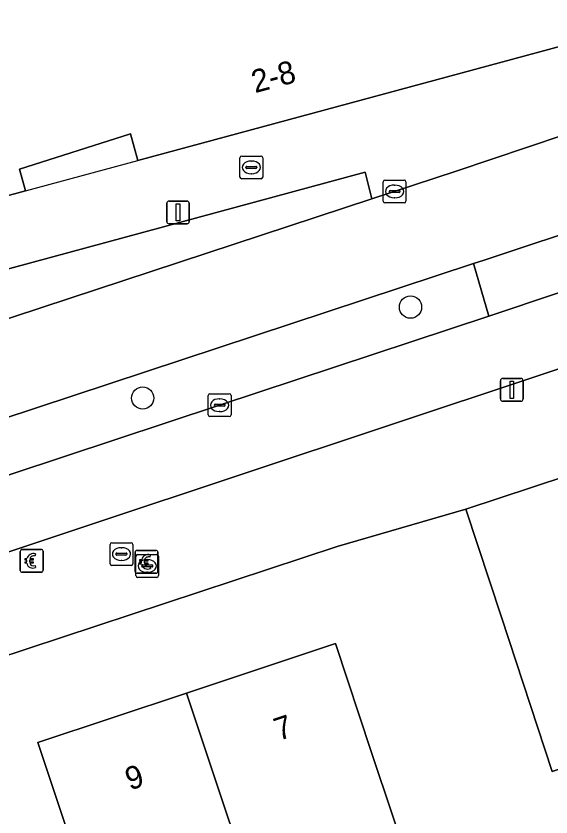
# Model space of a CAD drawing. Extents: x 161087 to 161926, y 382572 to 383873.
# Drawn here: x 161653.49 to 161676.98, y 382778.05 to 382813.22 of the extents above; entities that cross this region are included whole.
import ezdxf

# ---------------------------------------------------------------- set-up
doc = ezdxf.new("R2010")
doc.units = 0
for name, color, linetype in [('IMGEO_Berm_groen', 7, 'Continuous'), ('IMGEO_Berm_halfverhard', 7, 'Continuous'), ('IMGEO_Betaalautomaat', 7, 'Continuous'), ('IMGEO_Boom', 7, 'Continuous'), ('IMGEO_Brandkraan', 7, 'Continuous'), ('IMGEO_Erf', 7, 'Continuous'), ('IMGEO_Fietspad_gesloten', 7, 'Continuous'), ('IMGEO_Kolk', 7, 'Continuous'), ('IMGEO_Lichtmast', 7, 'Continuous'), ('IMGEO_Pand', 7, 'Continuous'), ('IMGEO_Pand_nummerreeks', 7, 'Continuous'), ('IMGEO_Pand_overbouw', 7, 'Continuous'), ('IMGEO_Rijbaan_lokaal_gesloten', 7, 'Continuous'), ('IMGEO_Rioolput', 7, 'Continuous'), ('IMGEO_Voetpad_open', 7, 'Continuous')]:
    doc.layers.add(name, color=color, linetype=linetype)

msp = doc.modelspace()

# ---------------------------------------------------------------- linework, layer by layer
at = {"layer": 'IMGEO_Berm_groen'}
for points in [[(161669.12, 382805.198), (161668.823, 382806.36), (161642.785, 382799.309), (161642.68, 382799.282), (161643.487, 382796.752), (161643.598, 382796.789), (161646.117, 382797.624)], [(161674.253, 382800.049), (161673.571, 382802.349), (161647.995, 382793.914), (161648.757, 382791.611), (161662.429, 382796.134)]]:
    msp.add_lwpolyline(points, close=True, dxfattribs=at)
at = {"layer": 'IMGEO_Berm_halfverhard'}
msp.add_lwpolyline([(161679.239, 382804.225), (161674.047, 382802.506), (161673.571, 382802.349), (161674.253, 382800.049), (161674.729, 382800.207), (161679.006, 382801.638), (161679.974, 382801.957)], close=True, dxfattribs=at)
at = {"layer": 'IMGEO_Betaalautomaat'}
for p, q in [((161653.675, 382788.875), (161653.675, 382789.716)), ((161653.675, 382789.716), (161653.675, 382788.875)), ((161653.75, 382789.799), (161654.591, 382789.799)), ((161654.591, 382789.799), (161653.75, 382789.799)), ((161654.674, 382789.725), (161654.674, 382788.884)), ((161654.674, 382788.884), (161654.674, 382789.725)), ((161658.717, 382788.832), (161658.717, 382789.673)), ((161658.717, 382789.673), (161658.717, 382788.832)), ((161658.792, 382789.756), (161659.633, 382789.756)), ((161659.633, 382789.756), (161658.792, 382789.756)), ((161659.716, 382789.682), (161659.716, 382788.841)), ((161659.716, 382788.841), (161659.716, 382789.682)), ((161653.958, 382789.263), (161653.958, 382789.331)), ((161654.079, 382789.331), (161654.079, 382789.263)), ((161654.337, 382789.604), (161654.32, 382789.504)), ((161659.379, 382789.561), (161659.362, 382789.461)), ((161654.324, 382789.098), (161654.346, 382789.011)), ((161659, 382789.22), (161659, 382789.288)), ((161659.121, 382789.288), (161659.121, 382789.22)), ((161659.366, 382789.055), (161659.388, 382788.968)), ((161654.6, 382788.8), (161653.759, 382788.8)), ((161653.759, 382788.8), (161654.6, 382788.8)), ((161659.642, 382788.757), (161658.801, 382788.757)), ((161658.801, 382788.757), (161659.642, 382788.757))]:
    msp.add_line(p, q, dxfattribs=at)
for points in [[(161653.958, 382789.331), (161653.889, 382789.331), (161653.889, 382789.4), (161653.968, 382789.4)], [(161654.09, 382789.4), (161654.237, 382789.4), (161654.237, 382789.331), (161654.079, 382789.331)], [(161659, 382789.288), (161658.931, 382789.288), (161658.931, 382789.357), (161659.01, 382789.357)], [(161659.132, 382789.357), (161659.279, 382789.357), (161659.279, 382789.288), (161659.121, 382789.288)], [(161653.963, 382789.194), (161653.889, 382789.194), (161653.889, 382789.263), (161653.958, 382789.263)], [(161654.079, 382789.263), (161654.237, 382789.263), (161654.237, 382789.194), (161654.093, 382789.194)], [(161659.005, 382789.151), (161658.931, 382789.151), (161658.931, 382789.22), (161659, 382789.22)], [(161659.121, 382789.22), (161659.279, 382789.22), (161659.279, 382789.151), (161659.135, 382789.151)]]:
    msp.add_lwpolyline(points, dxfattribs=at)
for centre, radius, start, end in [((161653.753, 382789.722), 0.0779, 92.4484, 184.2845), ((161653.753, 382789.722), 0.0779, 92.4484, 184.2845), ((161654.597, 382789.722), 0.0779, 2.4484, 94.2845), ((161654.597, 382789.722), 0.0779, 2.4484, 94.2845), ((161658.795, 382789.679), 0.0779, 92.4484, 184.2845), ((161658.795, 382789.679), 0.0779, 92.4484, 184.2845), ((161659.639, 382789.679), 0.0779, 2.4484, 94.2845), ((161659.639, 382789.679), 0.0779, 2.4484, 94.2845), ((161654.251, 382789.324), 0.293, 73.014, 165.0139), ((161654.257, 382789.337), 0.179, 69.3236, 159.5683), ((161659.293, 382789.281), 0.293, 73.014, 165.0139), ((161659.299, 382789.294), 0.179, 69.3236, 159.5683), ((161654.224, 382789.249), 0.267, 191.8096, 297.0389), ((161654.257, 382789.264), 0.179, 202.7625, 291.8693), ((161659.266, 382789.206), 0.267, 191.8096, 297.0389), ((161659.299, 382789.221), 0.179, 202.7625, 291.8693), ((161653.753, 382788.878), 0.0779, 182.4484, 274.2845), ((161653.753, 382788.878), 0.0779, 182.4484, 274.2845), ((161654.597, 382788.878), 0.0779, 272.4484, 4.2845), ((161654.597, 382788.878), 0.0779, 272.4484, 4.2845), ((161658.795, 382788.835), 0.0779, 182.4484, 274.2845), ((161658.795, 382788.835), 0.0779, 182.4484, 274.2845), ((161659.639, 382788.835), 0.0779, 272.4484, 4.2845), ((161659.639, 382788.835), 0.0779, 272.4484, 4.2845)]:
    msp.add_arc(centre, radius, start, end, dxfattribs=at)
at = {"layer": 'IMGEO_Boom'}
for centre in [(161670.812, 382800.441), (161659.053, 382796.447)]:
    msp.add_circle(centre, 0.489, dxfattribs=at)
at = {"layer": 'IMGEO_Brandkraan'}
for p, q in [((161658.749, 382788.65), (161658.749, 382789.502)), ((161658.824, 382789.576), (161659.676, 382789.576)), ((161659.237, 382789.356), (161659.262, 382789.356)), ((161659.75, 382789.502), (161659.75, 382788.65)), ((161659.008, 382789.07), (161659.008, 382789.082)), ((161659.446, 382789.033), (161659.048, 382789.033)), ((161659.051, 382789.119), (161659.449, 382789.119)), ((161659.492, 382789.082), (161659.492, 382789.07)), ((161659.26, 382788.796), (161659.235, 382788.796)), ((161659.676, 382788.576), (161658.824, 382788.576))]:
    msp.add_line(p, q, dxfattribs=at)
for points in [[(161658.749, 382788.65), (161658.749, 382789.502)], [(161658.824, 382789.576), (161659.676, 382789.576)], [(161659.75, 382789.502), (161659.75, 382788.65)], [(161659.676, 382788.576), (161658.824, 382788.576)]]:
    msp.add_lwpolyline(points, dxfattribs=at)
for centre, radius, start, end in [((161658.826, 382789.5), 0.0765, 91.552, 178.448), ((161658.826, 382789.5), 0.0765, 91.552, 178.448), ((161659.674, 382789.5), 0.0765, 1.552, 88.448), ((161659.674, 382789.5), 0.0765, 1.552, 88.448), ((161659.048, 382789.079), 0.0403, 85.8775, 175.7526), ((161659.045, 382789.069), 0.0366, 178.938, 274.7102), ((161659.449, 382789.076), 0.043, 264.8664, 352.4533), ((161659.453, 382789.081), 0.0386, 1.7309, 96.639), ((161658.826, 382788.652), 0.0765, 181.552, 268.448), ((161658.826, 382788.652), 0.0765, 181.552, 268.448), ((161659.674, 382788.652), 0.0765, 271.552, 358.448), ((161659.674, 382788.652), 0.0765, 271.552, 358.448)]:
    msp.add_arc(centre, radius, start, end, dxfattribs=at)
for centre, major_axis, ratio, start_param, end_param in [((161659.236, 382789.076), (-0.387, 0.002), 0.722429, 4.712389, 7.853982), ((161659.261, 382789.076), (-0.39, 0.002), 0.717154, 1.570796, 4.712389)]:
    msp.add_ellipse(centre, major_axis=major_axis, ratio=ratio, start_param=start_param, end_param=end_param, dxfattribs=at)
at = {"layer": 'IMGEO_Erf'}
msp.add_lwpolyline([(161712.955, 382781.187), (161710.53, 382787.424), (161708.527, 382792.577), (161702.9, 382790.39), (161703.029, 382790.057), (161700.892, 382787.466), (161700.822, 382787.646), (161694.622, 382780.114), (161693.332, 382781.441), (161693.557, 382783.201), (161689.279, 382781.794), (161686.574, 382780.904), (161683.613, 382779.93), (161683.448, 382779.876), (161682.763, 382781.94), (161681.287, 382781.455), (161677.03, 382780.056), (161674.804, 382786.826), (161673.242, 382791.575), (161667.594, 382789.929), (161637.427, 382779.982)], dxfattribs=at)
msp.add_lwpolyline([(161664.779, 382772.083), (161665.682, 382769.375), (161666.021, 382768.356), (161666.195, 382767.836), (161659.658, 382765.658), (161659.642, 382765.708), (161659.485, 382766.178), (161657.275, 382772.813), (161656.021, 382776.578), (161654.442, 382781.321), (161660.975, 382783.496), (161667.512, 382785.673), (161669.091, 382780.929), (161670.995, 382775.209), (161671.424, 382773.92), (161674.213, 382774.896), (161676.279, 382768.99), (161672.96, 382767.829), (161672.097, 382770.294), (161669.494, 382769.426), (161668.449, 382772.563), (161667.962, 382772.401), (161667.74, 382773.069)], close=True, dxfattribs=at)
at = {"layer": 'IMGEO_Fietspad_gesloten'}
for points in [[(161590.845, 382774.955), (161600.424, 382778.175), (161606.867, 382780.274), (161620.39, 382784.782), (161636.138, 382789.999), (161645.193, 382792.972), (161647.376, 382793.71), (161647.995, 382793.914), (161673.571, 382802.349), (161674.047, 382802.506), (161679.239, 382804.225), (161681.775, 382805.065), (161703.785, 382812.521), (161709.459, 382814.438)], [(161687.036, 382811.115), (161680.653, 382809.049), (161672.813, 382806.414), (161669.12, 382805.198), (161646.117, 382797.624), (161643.598, 382796.789), (161643.487, 382796.752), (161637.587, 382794.797), (161636.587, 382794.458), (161636.5, 382794.429), (161633.539, 382793.428), (161627.936, 382791.59), (161605.586, 382784.256), (161599.127, 382782.114), (161588.363, 382778.462)]]:
    msp.add_lwpolyline(points, dxfattribs=at)
at = {"layer": 'IMGEO_Kolk'}
for p, q in [((161663.323, 382806.148), (161663.323, 382807)), ((161663.398, 382807.074), (161664.25, 382807.074)), ((161664.324, 382807), (161664.324, 382806.148)), ((161663.582, 382806.568), (161663.582, 382806.58)), ((161664.02, 382806.531), (161663.622, 382806.531)), ((161663.625, 382806.617), (161664.023, 382806.617)), ((161663.811, 382806.854), (161663.836, 382806.854)), ((161664.066, 382806.58), (161664.066, 382806.568)), ((161663.834, 382806.294), (161663.809, 382806.294)), ((161664.25, 382806.074), (161663.398, 382806.074)), ((161661.928, 382795.708), (161661.928, 382796.56)), ((161662.003, 382796.634), (161662.855, 382796.634)), ((161662.416, 382796.414), (161662.441, 382796.414)), ((161662.929, 382796.56), (161662.929, 382795.708)), ((161662.187, 382796.128), (161662.187, 382796.14)), ((161662.625, 382796.091), (161662.227, 382796.091)), ((161662.23, 382796.177), (161662.628, 382796.177)), ((161662.671, 382796.14), (161662.671, 382796.128)), ((161662.855, 382795.634), (161662.003, 382795.634)), ((161662.439, 382795.854), (161662.414, 382795.854))]:
    msp.add_line(p, q, dxfattribs=at)
for points in [[(161663.323, 382806.148), (161663.323, 382807)], [(161663.398, 382807.074), (161664.25, 382807.074)], [(161664.324, 382807), (161664.324, 382806.148)], [(161664.25, 382806.074), (161663.398, 382806.074)], [(161661.928, 382795.708), (161661.928, 382796.56)], [(161662.003, 382796.634), (161662.855, 382796.634)], [(161662.929, 382796.56), (161662.929, 382795.708)], [(161662.855, 382795.634), (161662.003, 382795.634)]]:
    msp.add_lwpolyline(points, dxfattribs=at)
for centre, radius, start, end in [((161663.4, 382806.998), 0.0765, 91.552, 178.448), ((161663.4, 382806.998), 0.0765, 91.552, 178.448), ((161664.248, 382806.998), 0.0765, 1.552, 88.448), ((161664.248, 382806.998), 0.0765, 1.552, 88.448), ((161663.622, 382806.577), 0.0403, 85.8775, 175.7526), ((161663.619, 382806.567), 0.0366, 178.938, 274.7102), ((161664.023, 382806.574), 0.043, 264.8664, 352.4533), ((161664.027, 382806.579), 0.0386, 1.7309, 96.639), ((161663.4, 382806.15), 0.0765, 181.552, 268.448), ((161663.4, 382806.15), 0.0765, 181.552, 268.448), ((161664.248, 382806.15), 0.0765, 271.552, 358.448), ((161664.248, 382806.15), 0.0765, 271.552, 358.448), ((161662.005, 382796.558), 0.0765, 91.552, 178.448), ((161662.005, 382796.558), 0.0765, 91.552, 178.448), ((161662.853, 382796.558), 0.0765, 1.552, 88.448), ((161662.853, 382796.558), 0.0765, 1.552, 88.448), ((161662.227, 382796.137), 0.0403, 85.8775, 175.7526), ((161662.224, 382796.127), 0.0366, 178.938, 274.7102), ((161662.628, 382796.134), 0.043, 264.8664, 352.4533), ((161662.632, 382796.139), 0.0386, 1.7309, 96.639), ((161662.005, 382795.71), 0.0765, 181.552, 268.448), ((161662.005, 382795.71), 0.0765, 181.552, 268.448), ((161662.853, 382795.71), 0.0765, 271.552, 358.448), ((161662.853, 382795.71), 0.0765, 271.552, 358.448)]:
    msp.add_arc(centre, radius, start, end, dxfattribs=at)
for centre, major_axis, ratio, start_param, end_param in [((161663.81, 382806.574), (-0.387, 0.002), 0.722429, 4.712389, 7.853982), ((161663.835, 382806.574), (-0.39, 0.002), 0.717154, 1.570796, 4.712389), ((161662.415, 382796.134), (-0.387, 0.002), 0.722429, 4.712389, 7.853982), ((161662.44, 382796.134), (-0.39, 0.002), 0.717154, 1.570796, 4.712389)]:
    msp.add_ellipse(centre, major_axis=major_axis, ratio=ratio, start_param=start_param, end_param=end_param, dxfattribs=at)
at = {"layer": 'IMGEO_Lichtmast'}
for p, q in [((161660.107, 382804.197), (161660.107, 382804.997)), ((161660.107, 382804.997), (161660.107, 382804.197)), ((161660.207, 382805.097), (161660.997, 382805.097)), ((161660.997, 382805.097), (161660.207, 382805.097)), ((161661.097, 382804.997), (161661.097, 382804.197)), ((161661.097, 382804.197), (161661.097, 382804.997)), ((161660.997, 382804.097), (161660.207, 382804.097)), ((161660.207, 382804.097), (161660.997, 382804.097)), ((161674.762, 382796.409), (161674.762, 382797.209)), ((161674.762, 382797.209), (161674.762, 382796.409)), ((161674.862, 382797.309), (161675.652, 382797.309)), ((161675.652, 382797.309), (161674.862, 382797.309)), ((161675.752, 382797.209), (161675.752, 382796.409)), ((161675.752, 382796.409), (161675.752, 382797.209)), ((161675.652, 382796.309), (161674.862, 382796.309)), ((161674.862, 382796.309), (161675.652, 382796.309))]:
    msp.add_line(p, q, dxfattribs=at)
for points in [[(161660.527, 382804.972), (161660.677, 382804.972), (161660.677, 382804.222), (161660.527, 382804.222), (161660.527, 382804.972)], [(161675.182, 382797.184), (161675.332, 382797.184), (161675.332, 382796.434), (161675.182, 382796.434), (161675.182, 382797.184)]]:
    msp.add_lwpolyline(points, dxfattribs=at)
for centre, start, end in [((161660.207, 382804.997), 90, 180), ((161660.207, 382804.997), 90, 180), ((161660.997, 382804.997), 0, 90), ((161660.997, 382804.997), 360, 90), ((161660.207, 382804.197), 180, 270), ((161660.207, 382804.197), 180, 270), ((161660.997, 382804.197), 270, 0), ((161660.997, 382804.197), 270, 0), ((161674.862, 382797.209), 90, 180), ((161674.862, 382797.209), 90, 180), ((161675.652, 382797.209), 0, 90), ((161675.652, 382797.209), 360, 90), ((161674.862, 382796.409), 180, 270), ((161674.862, 382796.409), 180, 270), ((161675.652, 382796.409), 270, 0), ((161675.652, 382796.409), 270, 0)]:
    msp.add_arc(centre, 0.1, start, end, dxfattribs=at)
at = {"layer": 'IMGEO_Pand'}
for points in [[(161688.4, 382814.886), (161684.295, 382828.033), (161680.902, 382826.981), (161680.177, 382826.756), (161637.768, 382813.613), (161637.055, 382815.912), (161632.654, 382814.494), (161630.959, 382813.948), (161635.191, 382800.49), (161641.161, 382802.095), (161653.909, 382805.547), (161653.642, 382806.49), (161658.509, 382808.046), (161658.838, 382806.882)], [(161684.809, 382795.379), (161679.143, 382793.516), (161673.242, 382791.575), (161674.804, 382786.826), (161677.03, 382780.056), (161681.287, 382781.455), (161682.763, 382781.94), (161683.448, 382779.876), (161683.613, 382779.93), (161686.574, 382780.904), (161689.279, 382781.794), (161693.557, 382783.201), (161693.691, 382784.249), (161693.88, 382790.184), (161687.242, 382787.983)], [(161660.975, 382783.496), (161664.779, 382772.083), (161667.74, 382773.069), (161667.962, 382772.401), (161668.449, 382772.563), (161669.494, 382769.426), (161672.097, 382770.294), (161672.96, 382767.829), (161676.279, 382768.99), (161674.213, 382774.896), (161671.424, 382773.92), (161670.995, 382775.209), (161669.091, 382780.929), (161667.512, 382785.673)], [(161660.975, 382783.496), (161654.442, 382781.321), (161656.021, 382776.578), (161657.275, 382772.813), (161659.485, 382766.178), (161659.642, 382765.708), (161659.658, 382765.658), (161666.195, 382767.836), (161666.021, 382768.356), (161665.682, 382769.375), (161664.779, 382772.083)]]:
    msp.add_lwpolyline(points, close=True, dxfattribs=at)
at = {"layer": 'IMGEO_Pand_overbouw'}
msp.add_lwpolyline([(161658.838, 382806.882), (161658.509, 382808.046), (161653.642, 382806.49), (161653.909, 382805.547)], close=True, dxfattribs=at)
at = {"layer": 'IMGEO_Rijbaan_lokaal_gesloten'}
msp.add_lwpolyline([(161640.402, 382785.458), (161656.819, 382790.909), (161682.921, 382799.59), (161696.266, 382804.008), (161701.663, 382805.805), (161702.586, 382806.112), (161703.341, 382806.363), (161702.348, 382809.37), (161698.143, 382807.988), (161682.511, 382802.794), (161679.974, 382801.957), (161679.006, 382801.638), (161674.729, 382800.207), (161674.253, 382800.049), (161662.429, 382796.134), (161648.757, 382791.611), (161648.646, 382791.574), (161648.138, 382791.404), (161645.919, 382790.64), (161636.843, 382787.626)], dxfattribs=at)
at = {"layer": 'IMGEO_Rioolput'}
for p, q in [((161669.612, 382805.091), (161669.612, 382805.943)), ((161669.687, 382806.017), (161670.539, 382806.017)), ((161670.613, 382805.943), (161670.613, 382805.091)), ((161669.871, 382805.511), (161669.871, 382805.523)), ((161670.309, 382805.474), (161669.911, 382805.474)), ((161669.914, 382805.56), (161670.312, 382805.56)), ((161670.1, 382805.797), (161670.125, 382805.797)), ((161670.355, 382805.523), (161670.355, 382805.511)), ((161670.123, 382805.237), (161670.098, 382805.237)), ((161670.539, 382805.017), (161669.687, 382805.017)), ((161657.619, 382789.171), (161657.619, 382790.023)), ((161657.694, 382790.097), (161658.546, 382790.097)), ((161658.62, 382790.023), (161658.62, 382789.171)), ((161658.107, 382789.877), (161658.132, 382789.877)), ((161657.878, 382789.591), (161657.878, 382789.603)), ((161658.316, 382789.554), (161657.918, 382789.554)), ((161657.921, 382789.64), (161658.319, 382789.64)), ((161658.13, 382789.317), (161658.105, 382789.317)), ((161658.362, 382789.603), (161658.362, 382789.591)), ((161658.546, 382789.097), (161657.694, 382789.097))]:
    msp.add_line(p, q, dxfattribs=at)
for points in [[(161669.612, 382805.091), (161669.612, 382805.943)], [(161669.687, 382806.017), (161670.539, 382806.017)], [(161670.613, 382805.943), (161670.613, 382805.091)], [(161670.539, 382805.017), (161669.687, 382805.017)], [(161657.619, 382789.171), (161657.619, 382790.023)], [(161657.694, 382790.097), (161658.546, 382790.097)], [(161658.62, 382790.023), (161658.62, 382789.171)], [(161658.546, 382789.097), (161657.694, 382789.097)]]:
    msp.add_lwpolyline(points, dxfattribs=at)
for centre, radius, start, end in [((161669.689, 382805.941), 0.0765, 91.552, 178.448), ((161669.689, 382805.941), 0.0765, 91.552, 178.448), ((161670.537, 382805.941), 0.0765, 1.552, 88.448), ((161670.537, 382805.941), 0.0765, 1.552, 88.448), ((161669.911, 382805.52), 0.0403, 85.8775, 175.7526), ((161669.908, 382805.51), 0.0366, 178.938, 274.7102), ((161670.312, 382805.517), 0.043, 264.8664, 352.4533), ((161670.316, 382805.522), 0.0386, 1.7309, 96.639), ((161669.689, 382805.093), 0.0765, 181.552, 268.448), ((161669.689, 382805.093), 0.0765, 181.552, 268.448), ((161670.537, 382805.093), 0.0765, 271.552, 358.448), ((161670.537, 382805.093), 0.0765, 271.552, 358.448), ((161657.696, 382790.021), 0.0765, 91.552, 178.448), ((161657.696, 382790.021), 0.0765, 91.552, 178.448), ((161658.544, 382790.021), 0.0765, 1.552, 88.448), ((161658.544, 382790.021), 0.0765, 1.552, 88.448), ((161657.918, 382789.6), 0.0403, 85.8775, 175.7526), ((161657.915, 382789.59), 0.0366, 178.938, 274.7102), ((161658.319, 382789.597), 0.043, 264.8664, 352.4533), ((161658.323, 382789.602), 0.0386, 1.7309, 96.639), ((161657.696, 382789.173), 0.0765, 181.552, 268.448), ((161657.696, 382789.173), 0.0765, 181.552, 268.448), ((161658.544, 382789.173), 0.0765, 271.552, 358.448), ((161658.544, 382789.173), 0.0765, 271.552, 358.448)]:
    msp.add_arc(centre, radius, start, end, dxfattribs=at)
for centre, major_axis, ratio, start_param, end_param in [((161670.099, 382805.517), (-0.387, 0.002), 0.722429, 4.712389, 7.853982), ((161670.124, 382805.517), (-0.39, 0.002), 0.717154, 1.570796, 4.712389), ((161658.106, 382789.597), (-0.387, 0.002), 0.722429, 4.712389, 7.853982), ((161658.131, 382789.597), (-0.39, 0.002), 0.717154, 1.570796, 4.712389)]:
    msp.add_ellipse(centre, major_axis=major_axis, ratio=ratio, start_param=start_param, end_param=end_param, dxfattribs=at)
at = {"layer": 'IMGEO_Voetpad_open'}
for points in [[(161693.655, 382812.828), (161704.199, 382816.39), (161708.762, 382817.931), (161708.131, 382820.483), (161701.984, 382818.641), (161696.767, 382817.195), (161690.898, 382815.569), (161688.4, 382814.886), (161658.838, 382806.882), (161658.509, 382808.046), (161653.642, 382806.49), (161653.909, 382805.547), (161641.161, 382802.095), (161635.191, 382800.49), (161623.676, 382796.778)], [(161635.563, 382797.45), (161635.645, 382797.471), (161642.68, 382799.282), (161642.785, 382799.309), (161668.823, 382806.36), (161669.12, 382805.198), (161672.813, 382806.414), (161680.653, 382809.049), (161687.036, 382811.115)], [(161707.227, 382807.634), (161703.341, 382806.363), (161702.586, 382806.112), (161701.663, 382805.805), (161702.253, 382804.092), (161696.911, 382802.26), (161683.568, 382797.683), (161682.921, 382799.59), (161656.819, 382790.909), (161640.402, 382785.458), (161637.495, 382784.499), (161619.539, 382778.558), (161618.873, 382778.339), (161619.632, 382776.119), (161601.27, 382769.836), (161600.455, 382772.219), (161599.942, 382772.001), (161599.434, 382771.772)], [(161574.477, 382750.86), (161579.443, 382754.299), (161583.93, 382757.469), (161585.099, 382758.295), (161585.017, 382758.404), (161586.678, 382759.589), (161588.667, 382761.008), (161590.565, 382762.379), (161595.594, 382766.012), (161595.696, 382765.813), (161596.009, 382765.952), (161595.848, 382766.199), (161596.018, 382766.327), (161596.158, 382766.372), (161601.023, 382767.942), (161624.636, 382775.599), (161633.162, 382778.456), (161637.427, 382779.982), (161667.594, 382789.929), (161673.242, 382791.575), (161679.143, 382793.516), (161684.809, 382795.379)]]:
    msp.add_lwpolyline(points, dxfattribs=at)

# ---------------------------------------------------------------- texts
at = {"layer": 'IMGEO_Pand_nummerreeks'}
for s, rotation, p in [('2-8', 15.149, (161663.985, 382809.83)), ('7', 18.4165, (161665.02, 382781.387)), ('9', 18.4149, (161658.485, 382779.211))]:
    msp.add_text(s, height=1, rotation=rotation, dxfattribs=at).set_placement(p)

doc.saveas('drawing.dxf')
